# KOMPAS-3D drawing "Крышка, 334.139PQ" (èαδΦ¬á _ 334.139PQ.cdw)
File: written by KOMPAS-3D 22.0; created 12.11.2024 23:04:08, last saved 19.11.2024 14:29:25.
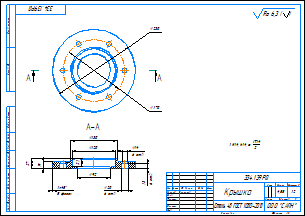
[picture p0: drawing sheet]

Sheet 1: A3, landscape

Document properties: Автор: aleksander.larionov.10@gmail.com; Знак неуказанной шероховатости: 4; Параметр неуказанной шероховатости: Ra 6,3; Полное имя файла: Крышка _ 334.139PQ.m3d; Масса: 4.58251

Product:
- Part/product: Крышка  | designation 334.139PQ
    Материал: Сталь 45 ГОСТ 1050-2013 (density 7810 kg/m3)
    Масса: 4.58251

Title block, sheet 1: Наименование: Крышка; designation: 334.139PQ; Материал: Сталь 45 ГОСТ 1050-2013; Масса: 4,58; Количество листов документа: 1; organisation: ООО "САЙН"; Форматы листов документа: A3; stored path: C:\Мои папки\Работа\Чертеж.cdt; Разработал: Ларионов

Views: Вид 1, Сверху, Разрез А-А
Referenced files in C:\Мои папки\Работа\Крышки, фланцы\334.139PQ\: Крышка _ 334.139PQ.m3d
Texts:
  Ra 6,3
  Ra 6,3 ( )
Dimensions and other numbers on the sheet: 230; 170; 334.139PQ; 1 H14, h14,    IT14 2 .; 20; 6 отв.; 14; 19; 13; 1; 5 фасок; 120; 92; 130; 27; 21; 1:2; 4,58; 334.139PQ Крышка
